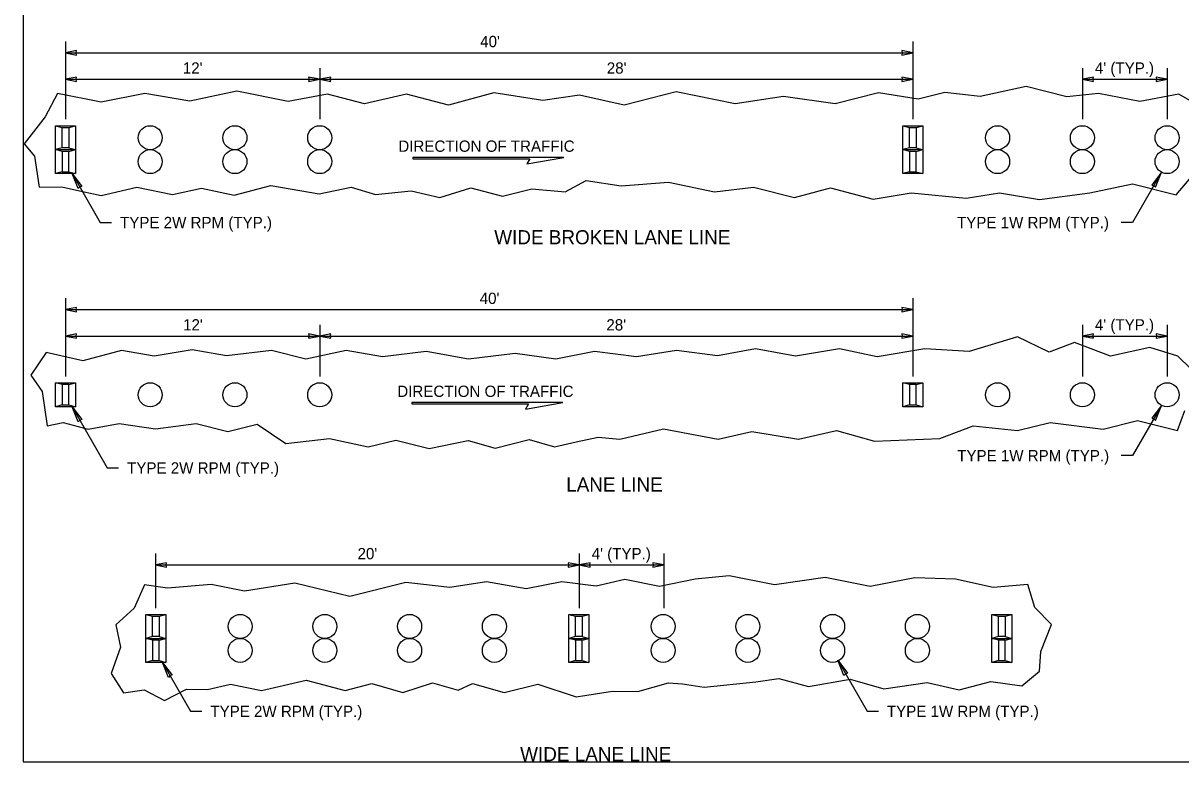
# Model space of a CAD drawing. Extents: x 99862 to 103151, y 100000 to 102076.
# Drawn here: x 99862 to 101501, y 100000 to 101045 of the extents above; entities that cross this region are included whole.
import ezdxf

# ---------------------------------------------------------------- set-up
doc = ezdxf.new("R2010")
doc.units = 0
for name, color, linetype in [('Level 1', 7, 'Continuous'), ('Level 11', 7, 'Continuous'), ('Level 15', 7, 'Continuous'), ('Level 20', 7, 'Continuous'), ('Level 3', 7, 'Continuous'), ('Level 50', 7, 'Continuous'), ('Level 60', 7, 'Continuous')]:
    doc.layers.add(name, color=color, linetype=linetype)

msp = doc.modelspace()

# ---------------------------------------------------------------- linework, layer by layer
at = {"layer": 'Level 1'}
msp.add_lwpolyline([(99862, 99999.5), (103151, 99999.5), (103151, 102075.5), (99862, 102075.5)], close=True, dxfattribs=at)
at = {"layer": 'Level 11'}
for p, q in [((99907.6, 100900), (99917.2, 100897.3)), ((99926.7, 100897.3), (99936.2, 100900)), ((101107.6, 100900), (101117.2, 100897.3)), ((101126.7, 100897.3), (101136.2, 100900)), ((99917.2, 100868.8), (99907.6, 100866.1)), ((99917.2, 100863.4), (99907.6, 100866.1)), ((99907.6, 100866.1), (99936.2, 100866.1)), ((99926.7, 100868.8), (99936.2, 100866.1)), ((99926.7, 100863.4), (99936.2, 100866.1)), ((101117.2, 100868.8), (101107.6, 100866.1)), ((101117.2, 100863.4), (101107.6, 100866.1)), ((101107.6, 100866.1), (101136.2, 100866.1)), ((101126.7, 100868.8), (101136.2, 100866.1)), ((101126.7, 100863.4), (101136.2, 100866.1)), ((99917.2, 100834.8), (99907.6, 100832.1)), ((99926.7, 100834.8), (99936.2, 100832.1)), ((101117.2, 100834.8), (101107.6, 100832.1)), ((101126.7, 100834.8), (101136.2, 100832.1)), ((99917.2, 100533.4), (99907.6, 100536.1)), ((99907.6, 100536.1), (99936.2, 100536.1)), ((99926.7, 100533.4), (99936.2, 100536.1)), ((101117.2, 100533.4), (101107.6, 100536.1)), ((101107.6, 100536.1), (101136.2, 100536.1)), ((101126.7, 100533.4), (101136.2, 100536.1)), ((99917.2, 100504.8), (99907.6, 100502.1)), ((99926.7, 100504.8), (99936.2, 100502.1)), ((101117.2, 100504.8), (101107.6, 100502.1)), ((101126.7, 100504.8), (101136.2, 100502.1)), ((100035.5, 100208.2), (100045, 100205.5)), ((100054.5, 100205.5), (100064, 100208.2)), ((100634.5, 100208.2), (100644, 100205.5)), ((100653.6, 100205.5), (100663.1, 100208.2)), ((101233.6, 100208.2), (101243.1, 100205.5)), ((101252.6, 100205.5), (101262.2, 100208.2)), ((100045, 100176.9), (100035.5, 100174.2)), ((100045, 100171.6), (100035.5, 100174.2)), ((100035.5, 100174.2), (100064, 100174.2)), ((100054.5, 100176.9), (100064, 100174.2)), ((100054.5, 100171.6), (100064, 100174.2)), ((100644, 100176.9), (100634.5, 100174.2)), ((100644, 100171.6), (100634.5, 100174.2)), ((100634.5, 100174.2), (100663.1, 100174.2)), ((100653.6, 100176.9), (100663.1, 100174.2)), ((100653.6, 100171.6), (100663.1, 100174.2)), ((101243.1, 100176.9), (101233.6, 100174.2)), ((101243.1, 100171.6), (101233.6, 100174.2)), ((101233.6, 100174.2), (101262.2, 100174.2)), ((101252.6, 100176.9), (101262.2, 100174.2)), ((101252.6, 100171.6), (101262.2, 100174.2)), ((100045, 100143), (100035.5, 100140.3)), ((100054.5, 100143), (100064, 100140.3)), ((100644, 100143), (100634.5, 100140.3)), ((100653.6, 100143), (100663.1, 100140.3)), ((101243.1, 100143), (101233.6, 100140.3)), ((101252.6, 100143), (101262.2, 100140.3))]:
    msp.add_line(p, q, dxfattribs=at)
for points in [[(99907.6, 100900), (99936.2, 100900), (99936.2, 100832.1), (99907.6, 100832.1)], [(99917.2, 100897.3), (99926.7, 100897.3), (99926.7, 100868.8), (99917.2, 100868.8)], [(101107.6, 100900), (101136.2, 100900), (101136.2, 100832.1), (101107.6, 100832.1)], [(101117.2, 100897.3), (101126.7, 100897.3), (101126.7, 100868.8), (101117.2, 100868.8)], [(99917.2, 100834.8), (99926.7, 100834.8), (99926.7, 100863.4), (99917.2, 100863.4)], [(101117.2, 100834.8), (101126.7, 100834.8), (101126.7, 100863.4), (101117.2, 100863.4)], [(99917.2, 100504.8), (99926.7, 100504.8), (99926.7, 100533.4), (99917.2, 100533.4)], [(101117.2, 100504.8), (101126.7, 100504.8), (101126.7, 100533.4), (101117.2, 100533.4)], [(100035.5, 100208.2), (100064, 100208.2), (100064, 100140.3), (100035.5, 100140.3)], [(100045, 100205.5), (100054.5, 100205.5), (100054.5, 100176.9), (100045, 100176.9)], [(100634.5, 100208.2), (100663.1, 100208.2), (100663.1, 100140.3), (100634.5, 100140.3)], [(100644, 100205.5), (100653.6, 100205.5), (100653.6, 100176.9), (100644, 100176.9)], [(101233.6, 100208.2), (101262.2, 100208.2), (101262.2, 100140.3), (101233.6, 100140.3)], [(101243.1, 100205.5), (101252.6, 100205.5), (101252.6, 100176.9), (101243.1, 100176.9)], [(100045, 100143), (100054.5, 100143), (100054.5, 100171.6), (100045, 100171.6)], [(100644, 100143), (100653.6, 100143), (100653.6, 100171.6), (100644, 100171.6)], [(101243.1, 100143), (101252.6, 100143), (101252.6, 100171.6), (101243.1, 100171.6)]]:
    msp.add_lwpolyline(points, close=True, dxfattribs=at)
for points in [[(99907.6, 100536.1), (99936.2, 100536.1)], [(99936.2, 100536.1), (99936.2, 100502.1), (99907.6, 100502.1), (99907.6, 100536.1)], [(101107.6, 100536.1), (101136.2, 100536.1)], [(101136.2, 100536.1), (101136.2, 100502.1), (101107.6, 100502.1), (101107.6, 100536.1)]]:
    msp.add_lwpolyline(points, dxfattribs=at)
for centre in [(100041.9, 100883), (100161.9, 100883), (100281.9, 100883), (101241.9, 100883), (101361.9, 100883), (101481.9, 100883), (100041.9, 100849.1), (100161.9, 100849.1), (100281.9, 100849.1), (101241.9, 100849.1), (101361.9, 100849.1), (101481.9, 100849.1), (100041.9, 100519.1), (100161.9, 100519.1), (100281.9, 100519.1), (101241.9, 100519.1), (101361.9, 100519.1), (101481.9, 100519.1), (100169.3, 100191.2), (100289.3, 100191.2), (100409.3, 100191.2), (100529.3, 100191.2), (100768.3, 100191.2), (100888.3, 100191.2), (101008.3, 100191.2), (101128.3, 100191.2), (100169.3, 100157.3), (100289.3, 100157.3), (100409.3, 100157.3), (100529.3, 100157.3), (100768.3, 100157.3), (100888.3, 100157.3), (101008.3, 100157.3), (101128.3, 100157.3)]:
    msp.add_circle(centre, 17, dxfattribs=at)
at = {"layer": 'Level 15'}
for p, q in [((99921.9, 101019.1), (99921.9, 100909)), ((101121.9, 101019.1), (101121.9, 100909)), ((99921.9, 101003.1), (101121.9, 101003.1)), ((100281.9, 100981.6), (100281.9, 100909)), ((101361.9, 100981.6), (101361.9, 100909)), ((101481.9, 100981.6), (101481.9, 100909)), ((99921.9, 100965.6), (100281.9, 100965.6)), ((100281.9, 100965.6), (101121.9, 100965.6)), ((101361.9, 100965.6), (101481.9, 100965.6)), ((99931.2, 100832.1), (99971.2, 100762.9)), ((101474.1, 100834.1), (101433, 100762.9)), ((99971.2, 100762.9), (99987.2, 100762.9)), ((101433, 100762.9), (101417, 100762.9)), ((99921.9, 100655.6), (99921.9, 100545.1)), ((101121.9, 100655.6), (101121.9, 100545.1)), ((99921.9, 100639.6), (101121.9, 100639.6)), ((100281.9, 100618.1), (100281.9, 100545.1)), ((101361.9, 100618.1), (101361.9, 100545.1)), ((101481.9, 100618.1), (101481.9, 100545.1)), ((99921.9, 100602.1), (100281.9, 100602.1)), ((100281.9, 100602.1), (101121.9, 100602.1)), ((101361.9, 100602.1), (101481.9, 100602.1)), ((99931.2, 100502.1), (99981.2, 100415.5)), ((101474.1, 100504.1), (101433, 100432.9)), ((101433, 100432.9), (101417, 100432.9)), ((99981.2, 100415.5), (99997.2, 100415.5)), ((100049.3, 100294.2), (100049.3, 100217.2)), ((100649.3, 100294.2), (100649.3, 100217.2)), ((100769.3, 100294.2), (100769.3, 100217.2)), ((100049.3, 100278.2), (100649.3, 100278.2)), ((100649.3, 100278.2), (100769.3, 100278.2)), ((100059.1, 100140.3), (100099.1, 100071)), ((101015.5, 100143.2), (101057.1, 100071)), ((100099.1, 100071), (100115.1, 100071)), ((101057.1, 100071), (101073.1, 100071))]:
    msp.add_line(p, q, dxfattribs=at)
for points in [[(99921.9, 101003.1), (99937.7, 101000), (99936.9, 101003.1), (99937.7, 101006.2)], [(101121.9, 101003.1), (101106.2, 101006.2), (101106.9, 101003.1), (101106.2, 101000)], [(99921.9, 100965.6), (99937.7, 100962.5), (99936.9, 100965.6), (99937.7, 100968.7)], [(100281.9, 100965.6), (100266.2, 100968.7), (100266.9, 100965.6), (100266.2, 100962.5)], [(100281.9, 100965.6), (100297.7, 100962.5), (100296.9, 100965.6), (100297.7, 100968.7)], [(101121.9, 100965.6), (101106.2, 100968.7), (101106.9, 100965.6), (101106.2, 100962.5)], [(101361.9, 100965.6), (101377.7, 100962.5), (101376.9, 100965.6), (101377.7, 100968.7)], [(101481.9, 100965.6), (101466.2, 100968.7), (101466.9, 100965.6), (101466.2, 100962.5)], [(99931.2, 100832.1), (99945.2, 100813.9), (99942.1, 100813.3), (99940.1, 100810.9)], [(101474.1, 100834.1), (101460.1, 100815.8), (101463.2, 100815.2), (101465.3, 100812.8)], [(99921.9, 100639.6), (99937.7, 100636.5), (99936.9, 100639.6), (99937.7, 100642.7)], [(101121.9, 100639.6), (101106.2, 100642.7), (101106.9, 100639.6), (101106.2, 100636.5)], [(99921.9, 100602.1), (99937.7, 100599), (99936.9, 100602.1), (99937.7, 100605.2)], [(100281.9, 100602.1), (100266.2, 100605.2), (100266.9, 100602.1), (100266.2, 100599)], [(100281.9, 100602.1), (100297.7, 100599), (100296.9, 100602.1), (100297.7, 100605.2)], [(101121.9, 100602.1), (101106.2, 100605.2), (101106.9, 100602.1), (101106.2, 100599)], [(101361.9, 100602.1), (101377.7, 100599), (101376.9, 100602.1), (101377.7, 100605.2)], [(101481.9, 100602.1), (101466.2, 100605.2), (101466.9, 100602.1), (101466.2, 100599)], [(99931.2, 100502.1), (99945.2, 100483.9), (99942.1, 100483.3), (99940.1, 100480.9)], [(101474.1, 100504.1), (101460.1, 100485.8), (101463.2, 100485.2), (101465.3, 100482.8)], [(100049.3, 100278.2), (100065, 100275.1), (100064.3, 100278.2), (100065, 100281.3)], [(100649.3, 100278.2), (100633.6, 100281.3), (100634.3, 100278.2), (100633.6, 100275.1)], [(100649.3, 100278.2), (100665, 100275.1), (100664.3, 100278.2), (100665, 100281.3)], [(100769.3, 100278.2), (100753.6, 100281.3), (100754.3, 100278.2), (100753.6, 100275.1)], [(100059.1, 100140.3), (100073.1, 100122), (100070, 100121.5), (100067.9, 100119)], [(101015.5, 100143.2), (101029.5, 100124.9), (101026.4, 100124.3), (101024.3, 100121.9)]]:
    msp.add_lwpolyline(points, close=True, dxfattribs=at)
at = {"layer": 'Level 20'}
msp.add_line((100701.9, 100965.6), (100794.2, 100965.6), dxfattribs=at)
at = {"layer": 'Level 3'}
for points in [[(100413.8, 100853.2), (100579.3, 100853.2), (100575.1, 100845.8), (100627.5, 100855), (100413.8, 100855)], [(100412.3, 100506.1), (100577.8, 100506.1), (100573.5, 100498.7), (100626, 100508), (100412.3, 100508)]]:
    msp.add_lwpolyline(points, close=True, dxfattribs=at)
at = {"layer": 'Level 50'}
for points in [[(101536.3, 100922.9), (101498.7, 100944.7), (101443.3, 100934.1), (101384.7, 100945.5), (101340, 100940.6), (101282.2, 100955.3), (101217.1, 100941.4), (101167.4, 100947.1), (101129.2, 100937.4), (101073, 100946.3), (101012, 100930.8), (100938.7, 100941.4), (100870.3, 100930.8), (100786.5, 100947.9), (100713.2, 100929.2), (100649.7, 100943.1), (100597.7, 100935.7), (100528.5, 100946.3), (100464.2, 100929.2), (100404.8, 100944.7), (100345.3, 100930.8), (100293.2, 100944.7), (100237.1, 100934.1), (100164.6, 100948.8), (100097.9, 100934.9), (100034.4, 100945.5), (99972.5, 100933.3), (99910.7, 100945.5), (99893, 100912.3), (99863.5, 100874.3), (99878.3, 100857)], [(99878.3, 100857), (99884.8, 100813), (99917, 100813.4), (99933.4, 100809.8), (99972.3, 100801.2), (100023.2, 100813), (100073.3, 100802.4), (100114.4, 100811.4), (100160.8, 100801.6), (100212.7, 100815.3), (100281.2, 100803.3), (100326.6, 100812.8), (100361, 100802.4), (100411.3, 100807.9), (100452.2, 100798.4), (100495.9, 100812), (100540.9, 100800), (100582.2, 100810.4), (100629.6, 100806.5), (100659.5, 100822.6), (100708.6, 100814.7), (100775.9, 100820.2), (100841, 100806.3), (100896.4, 100812.8), (100954.2, 100798.2), (101005.4, 100812), (101065.9, 100795.9), (101119.6, 100804.9), (101197.3, 100797.6), (101244.7, 100804.7), (101301.1, 100795.5), (101372.7, 100804.9), (101432.8, 100817.7), (101494.8, 100802), (101537.1, 100852.1)], [(101515.1, 100556.5), (101497.2, 100573.6), (101457.3, 100585.8), (101401.9, 100573.6), (101350.7, 100593.2), (101314.8, 100579.3), (101270.1, 100601.3), (101201.7, 100580.1), (101139, 100584.2), (101071.5, 100572.8), (101017.8, 100584.2), (100955.9, 100573.6), (100898.9, 100584.2), (100845.2, 100574.4), (100787.4, 100581.8), (100730.4, 100572.8), (100671, 100580.1), (100616.5, 100569.6), (100558.7, 100577.7), (100492.8, 100569.6), (100432.5, 100580.1), (100370.7, 100572.8), (100319.4, 100581.8), (100262.4, 100569.6), (100213.6, 100581.8), (100150.1, 100574.4), (100101.3, 100582.6), (100047.5, 100573.6), (100001.1, 100581.8), (99946.6, 100567.1), (99894.7, 100578.7), (99873.1, 100546.6), (99889, 100523.8)], [(99889, 100523.8), (99895.9, 100475.3), (99918.7, 100479.8), (99953.9, 100470.3), (99997.9, 100478.4), (100049.2, 100471.1), (100107, 100478.4), (100151.7, 100467), (100193.2, 100477.6), (100233.9, 100449.9), (100295.8, 100457.2), (100350.5, 100445.2), (100389.6, 100454.8), (100436.8, 100442.8), (100492.1, 100454.2), (100530.4, 100443.6), (100578.4, 100455.8), (100614.2, 100445.2), (100645.2, 100452.6), (100676.1, 100458.9), (100706.8, 100456.4), (100768.7, 100471.1), (100846, 100456.4), (100894, 100467), (100960, 100456.4), (101013.7, 100468.6), (101067.6, 100453.2), (101160.2, 100457.2), (101207.4, 100475.1), (101270.1, 100468.6), (101316.5, 100480), (101391.4, 100470.3), (101440.2, 100482.5), (101496.6, 100468.4), (101506.9, 100496.7)]]:
    msp.add_lwpolyline(points, dxfattribs=at)
msp.add_lwpolyline([(99986.5, 100124.4), (100004.1, 100097.2), (100033.2, 100101.4), (100062.3, 100086.1), (100093.1, 100102.3), (100123, 100102), (100155.5, 100109.4), (100199.5, 100100.4), (100263, 100115.1), (100317.8, 100100.6), (100355.8, 100110.2), (100399.7, 100097.7), (100441.9, 100111.4), (100478.2, 100100.8), (100498.4, 100110.5), (100543.2, 100097.5), (100590.8, 100109.6), (100644.9, 100091.7), (100696.6, 100099.4), (100732.4, 100099), (100775.8, 100111.5), (100795.9, 100110), (100826.2, 100105.3), (100899.7, 100112.9), (100932, 100117.5), (100974.3, 100106.1), (101033, 100116.7), (101081, 100102.8), (101142, 100111.8), (101187.6, 100101.2), (101232.4, 100113.4), (101276.3, 100106.9), (101286.9, 100115.9), (101301.4, 100127.9), (101303, 100155.6), (101318.4, 100193.8), (101294.4, 100217.9), (101284.7, 100250.5), (101235.4, 100246.2), (101182.5, 100258.1), (101124.7, 100259.8), (101061.2, 100247.5), (100997.8, 100260.6), (100926.1, 100250), (100861.8, 100263), (100813.8, 100258.1), (100762.9, 100247.5), (100714.1, 100257.7), (100673.4, 100248), (100624.8, 100254.5), (100574.5, 100244.3), (100518.3, 100254.1), (100466.2, 100246.3), (100404, 100253.2), (100324.6, 100233.7), (100246.9, 100252.4), (100175.3, 100241), (100128.3, 100250.4), (100066.2, 100245.1), (100033.6, 100250), (100019.4, 100217), (99993.2, 100193.4), (99999.9, 100161.7)], close=True, dxfattribs=at)
at = {"layer": 'Level 60'}
msp.add_line((99862, 99999.5), (99862, 99999.5), dxfattribs=at)

# ---------------------------------------------------------------- texts
at = {"layer": 'Level 20'}
for s, p in [("40'", (100509.2, 101011.1)), ("12'", (100088.1, 100973.6)), ("28'", (100688.5, 100973.6)), ("4' (TYP.)", (101379.7, 100973.6)), ("40'", (100508.5, 100647.6)), ("12'", (100088.5, 100610.1)), ("28'", (100687.9, 100610.1)), ("4' (TYP.)", (101379.7, 100610.1)), ("20'", (100335.5, 100286.2)), ("4' (TYP.)", (100667.1, 100286.2))]:
    msp.add_text(s, height=16, rotation=0, dxfattribs=at).set_placement(p)
for s, height, p in [('DIRECTION OF TRAFFIC', 16, (100393.3, 100863)), ('TYPE 2W RPM (TYP.)', 16, (99999.2, 100754.9)), ('TYPE 1W RPM (TYP.)', 16, (101184.4, 100754.9)), ('WIDE BROKEN LANE LINE', 20, (100529.1, 100732.1)), ('DIRECTION OF TRAFFIC', 16, (100391.8, 100516)), ('TYPE 1W RPM (TYP.)', 16, (101184.7, 100424.9)), ('TYPE 2W RPM (TYP.)', 16, (100009.2, 100407.5)), ('LANE LINE', 20, (100631, 100382.1)), ('TYPE 2W RPM (TYP.)', 16, (100127.1, 100063)), ('TYPE 1W RPM (TYP.)', 16, (101085.1, 100063)), ('WIDE LANE LINE', 20, (100565.8, 100000.3))]:
    msp.add_text(s, height=height, dxfattribs=at).set_placement(p)

doc.saveas('drawing.dxf')
